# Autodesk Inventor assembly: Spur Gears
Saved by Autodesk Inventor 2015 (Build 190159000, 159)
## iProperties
Created: 2014-06
Part Number: Spur Gears
Document SubType Name: Assembly
Designer: User
Categories: <?xml version="1.0" encoding="UTF-16"?> <MemberInstance><Categories><FamilyTemplate/><ParamToTemplateMap><ParamToTemplate><ParamToTemplate CategoryParameter="//
ClientObjectVersion: 1
Author: User
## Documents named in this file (3)
- Z:\CAD Files\Misc\Belt_Gear_Assembly\Design Accelerator\Spur Gears1.iam
- Z:\CAD Files\Misc\Belt_Gear_Assembly\Design Accelerator\Spur Gear11.ipt
- Z:\CAD Files\Misc\Belt_Gear_Assembly\Design Accelerator\Spur Gear22.ipt
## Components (2 placed, 2 different names)
1. Spur Gear1:1 — Rotation:1
2. Spur Gear2:1 — Rotation:1
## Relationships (1: RelateRotation 1)
- Rotation:1 [RelateRotation]: Spur Gear1:1 ↔ Spur Gear2:1
